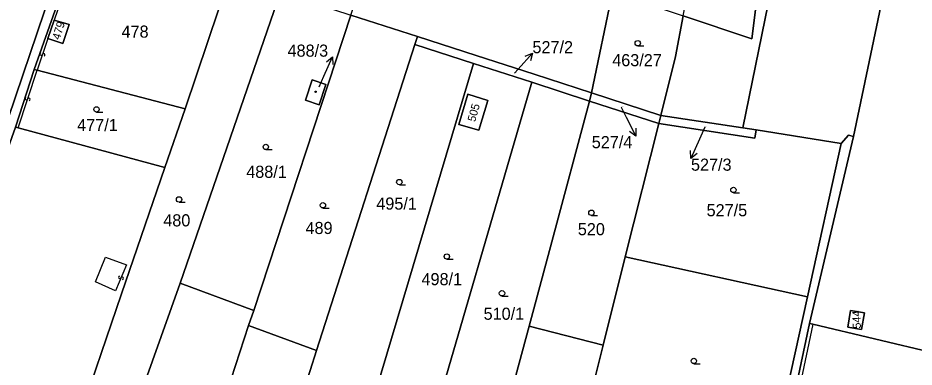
# Model space of a CAD drawing. Extents: x -600309 to -598967, y -1161267 to -1160292.
# Drawn here: x -599978 to -599852.3, y -1161077.3 to -1161028.3 of the extents above; entities that cross this region are included whole.
import ezdxf

# ---------------------------------------------------------------- set-up
doc = ezdxf.new("R2010")
doc.units = 0
for name, color, linetype in [('Level 1', 7, 'Continuous'), ('Level 13', 7, 'Continuous'), ('Level 3', 7, 'Continuous'), ('Level 4', 7, 'Continuous'), ('Level 5', 7, 'Continuous'), ('Level 57', 7, 'Continuous'), ('Level 60', 7, 'Continuous')]:
    doc.layers.add(name, color=color, linetype=linetype)

msp = doc.modelspace()

# ---------------------------------------------------------------- linework, layer by layer
at = {"layer": 'Level 1'}
for points in [[(-599876.36, -1161043.7), (-599856.42, -1160946.13), (-599839.99, -1160887.27), (-599850.14, -1160882.08)], [(-599860.84, -1161044.91), (-599844.27, -1160965.95)], [(-599884.69, -1161027.98), (-599875.08, -1161031.22), (-599871.19, -1161000.25), (-599876.49, -1160986.49)], [(-599987.63, -1161066.84), (-599982.42, -1161051.36), (-599970.18, -1161015.28)], [(-599968.71, -1161015.76), (-599975.67, -1161035.5)], [(-599948.21, -1161022.23), (-599954.53, -1161041.04)], [(-599941.17, -1161024.62), (-599955.2, -1161065.48)], [(-599897.54, -1161038.8), (-599894.62, -1161024.63)], [(-599972.87, -1161028.58), (-599970.76, -1161029.2), (-599971.67, -1161031.85), (-599973.77, -1161031.19)], [(-599973.77, -1161031.19), (-599972.87, -1161028.58)], [(-599931.3, -1161027.88), (-599944.9, -1161069.34)], [(-599931.3, -1161027.88), (-599921.93, -1161030.89)], [(-599884.69, -1161027.98), (-599885.79, -1161033.71), (-599887.83, -1161041.95)], [(-599921.93, -1161030.89), (-599922.3, -1161032.03)], [(-599921.93, -1161030.89), (-599913.74, -1161033.56), (-599905.6, -1161036.16), (-599897.54, -1161038.8)], [(-599922.3, -1161032.03), (-599936.1, -1161074.93)], [(-599922.3, -1161032.03), (-599914.08, -1161034.68)], [(-599914.08, -1161034.68), (-599927.85, -1161080.81)], [(-599914.08, -1161034.68), (-599905.93, -1161037.31)], [(-599975.67, -1161035.5), (-599978.31, -1161043.6)], [(-599975.67, -1161035.5), (-599975.27, -1161035.6)], [(-599975.27, -1161035.6), (-599954.53, -1161041.04)], [(-599936.71, -1161036.98), (-599934.81, -1161037.61), (-599935.75, -1161040.46), (-599937.65, -1161039.83), (-599936.71, -1161036.98)], [(-599905.93, -1161037.31), (-599921.39, -1161090.4)], [(-599905.93, -1161037.31), (-599897.85, -1161039.96)], [(-599914.87, -1161038.99), (-599912.09, -1161039.86), (-599913.34, -1161044.05), (-599916.13, -1161043.22), (-599914.87, -1161038.99)], [(-599897.85, -1161039.96), (-599903.12, -1161059.71), (-599906.31, -1161071.52)], [(-599897.54, -1161038.8), (-599897.85, -1161039.96)], [(-599897.85, -1161039.96), (-599888.12, -1161043.11)], [(-599897.54, -1161038.8), (-599887.83, -1161041.95)], [(-599954.53, -1161041.04), (-599957.36, -1161049.29)], [(-599888.12, -1161043.11), (-599887.83, -1161041.95)], [(-599887.83, -1161041.95), (-599876.36, -1161043.7)], [(-599977.92, -1161043.71), (-599978.31, -1161043.6)], [(-599957.36, -1161049.29), (-599977.92, -1161043.71)], [(-599888.12, -1161043.11), (-599892.84, -1161061.79)], [(-599888.12, -1161043.11), (-599874.67, -1161045.17), (-599874.48, -1161043.99)], [(-599876.36, -1161043.7), (-599874.48, -1161043.99)], [(-599874.48, -1161043.99), (-599862.56, -1161045.91)], [(-599867, -1161071.15), (-599860.84, -1161044.91)], [(-599862.56, -1161045.91), (-599861.52, -1161044.73), (-599860.84, -1161044.91)], [(-599862.56, -1161045.91), (-599867.28, -1161067.4)], [(-599969.84, -1161085.78), (-599963.43, -1161066.98), (-599957.36, -1161049.29)], [(-599895.94, -1161074.2), (-599892.84, -1161061.79)], [(-599892.84, -1161061.79), (-599867.28, -1161067.4)], [(-599955.2, -1161065.48), (-599962.99, -1161087.27)], [(-599955.2, -1161065.48), (-599944.9, -1161069.34)], [(-599867.28, -1161067.4), (-599877.21, -1161112.63)], [(-599944.9, -1161069.34), (-599945.61, -1161071.42)], [(-599861.26, -1161069.35), (-599859.28, -1161069.64), (-599859.69, -1161071.99), (-599861.6, -1161071.66), (-599861.26, -1161069.35)], [(-599872.88, -1161098.99), (-599867, -1161071.15)], [(-599866.54, -1161071.27), (-599867, -1161071.15)], [(-599845.34, -1161075.68), (-599849.26, -1161075.35), (-599866.54, -1161071.27)], [(-599945.61, -1161071.42), (-599948.08, -1161078.93)], [(-599936.1, -1161074.93), (-599945.61, -1161071.42)], [(-599906.31, -1161071.52), (-599914.53, -1161101.98)], [(-599906.31, -1161071.52), (-599895.94, -1161074.2)], [(-599936.1, -1161074.93), (-599936.97, -1161077.75)], [(-599895.94, -1161074.2), (-599903.23, -1161103.39)]]:
    msp.add_lwpolyline(points, dxfattribs=at)
at = {"layer": 'Level 13'}
for centre, start, end in [((-599974.69, -1161033.34), 108.3733, 340.9633), ((-599974.35, -1161033.46), 288.5877, 160.6857), ((-599976.77, -1161039.6), 109.2776, 341.3756), ((-599976.43, -1161039.72), 289.0631, 161.6531), ((-599963.68, -1161064.68), 104.5053, 337.0953), ((-599963.34, -1161064.82), 284.7198, 156.8178)]:
    msp.add_arc(centre, 0.184, start, end, dxfattribs=at)
at = {"layer": 'Level 3'}
for points in [[(-599968.48, -1161015.84), (-599972.87, -1161028.58)], [(-599973.77, -1161031.19), (-599975.27, -1161035.6)], [(-599977.92, -1161043.71), (-599975.27, -1161035.6)], [(-599967.09, -1161065.32), (-599965.69, -1161061.86), (-599962.74, -1161062.9), (-599964.28, -1161066.59), (-599967.09, -1161065.32)], [(-599866.54, -1161071.27), (-599872.38, -1161099)]]:
    msp.add_lwpolyline(points, dxfattribs=at)
at = {"layer": 'Level 5'}
for p, q in [((-599891.07, -1161032.21), (-599890.2, -1161032.21)), ((-599966.94, -1161041.49), (-599966.07, -1161041.49)), ((-599943.2, -1161046.76), (-599942.33, -1161046.76)), ((-599924.49, -1161051.69), (-599923.61, -1161051.69)), ((-599877.66, -1161052.8), (-599876.79, -1161052.8)), ((-599955.37, -1161054.13), (-599954.49, -1161054.13)), ((-599935.2, -1161054.95), (-599934.33, -1161054.95)), ((-599897.57, -1161056), (-599896.7, -1161056)), ((-599917.83, -1161062.13), (-599916.95, -1161062.13)), ((-599910.1, -1161067.3), (-599909.22, -1161067.3)), ((-599883.21, -1161076.79), (-599882.33, -1161076.79))]:
    msp.add_line(p, q, dxfattribs=at)
for centre, radius in [((-599891.07, -1161031.83), 0.375), ((-599936.23, -1161038.64), 0.09), ((-599936.23, -1161038.64), 0.0521), ((-599966.94, -1161041.11), 0.375), ((-599943.2, -1161046.38), 0.375), ((-599924.49, -1161051.31), 0.375), ((-599877.66, -1161052.42), 0.375), ((-599955.37, -1161053.75), 0.375), ((-599935.2, -1161054.57), 0.375), ((-599897.57, -1161055.62), 0.375), ((-599917.83, -1161061.75), 0.375), ((-599910.1, -1161066.92), 0.375), ((-599883.21, -1161076.41), 0.375)]:
    msp.add_circle(centre, radius, dxfattribs=at)
at = {"layer": 'Level 57'}
for p, q in [((-599907.83, -1161035.46), (-599905.83, -1161033.23)), ((-599935.07, -1161036.46), (-599933.85, -1161033.72)), ((-599908.33, -1161036.02), (-599907.83, -1161035.46)), ((-599935.72, -1161037.94), (-599935.07, -1161036.46)), ((-599893.41, -1161040.82), (-599892.7, -1161042.2)), ((-599892.7, -1161042.2), (-599891.32, -1161044.86)), ((-599881.68, -1161043.59), (-599882.41, -1161045.27)), ((-599882.41, -1161045.27), (-599883.61, -1161048.02))]:
    msp.add_line(p, q, dxfattribs=at)
for points in [[(-599906.87, -1161033.64), (-599905.83, -1161033.23), (-599906.12, -1161034.31)], [(-599934.71, -1161034.43), (-599933.85, -1161033.72), (-599933.8, -1161034.84)], [(-599891.33, -1161043.74), (-599891.32, -1161044.86), (-599892.22, -1161044.2)], [(-599882.75, -1161047.3), (-599883.61, -1161048.02), (-599883.67, -1161046.9)]]:
    msp.add_lwpolyline(points, dxfattribs=at)
at = {"layer": 'Level 60'}
for points in [[(-599844.27, -1160965.95), (-599860.84, -1161044.91), (-599861.52, -1161044.73), (-599862.56, -1161045.91), (-599874.48, -1161043.99), (-599876.36, -1161043.7), (-599856.42, -1160946.13), (-599839.99, -1160887.27), (-599850.14, -1160882.08), (-599827.83, -1160814.61), (-599810.16, -1160810.02), (-599816.36, -1160847.18), (-599843.15, -1160960.89)], [(-599853.73, -1160897.91), (-599855.26, -1160896.72), (-599850.14, -1160882.08), (-599839.99, -1160887.27), (-599856.42, -1160946.13), (-599876.36, -1161043.7), (-599887.83, -1161041.95), (-599885.79, -1161033.71), (-599884.69, -1161027.98), (-599875.08, -1161031.22), (-599871.19, -1161000.25), (-599876.49, -1160986.49), (-599876.14, -1160984.81), (-599874.2, -1160983.28), (-599869.25, -1160978.32), (-599867.01, -1160974.06), (-599865.26, -1160969.53), (-599852.15, -1160910.27), (-599851.34, -1160903.95)], [(-599843.15, -1160960.89), (-599827.13, -1160965.43), (-599827.7, -1160967.24), (-599825.39, -1160967.94), (-599824.75, -1160966.15), (-599821.88, -1160966.97), (-599822.87, -1160971.79), (-599825.9, -1160986.2), (-599831.06, -1161008.01), (-599832.98, -1161007.59), (-599833.44, -1161009.63), (-599831.55, -1161010.01), (-599837.23, -1161035.15), (-599845.34, -1161075.68), (-599849.26, -1161075.35), (-599866.54, -1161071.27), (-599867, -1161071.15), (-599860.84, -1161044.91), (-599844.27, -1160965.95)], [(-599871.19, -1161000.25), (-599875.08, -1161031.22), (-599884.69, -1161027.98), (-599876.49, -1160986.49)], [(-600026.92, -1160993.46), (-599990.21, -1161005.96), (-599990.65, -1161007.08), (-599990.72, -1161007.63), (-599989.7, -1161008.08), (-599989.91, -1161009.12), (-599988.76, -1161009.47), (-599970.18, -1161015.28), (-599982.42, -1161051.36), (-599987.63, -1161066.84), (-599993.68, -1161065.11), (-599995.07, -1161065.69), (-600005.59, -1161062.74), (-600019.19, -1161058.92), (-600026.96, -1161056.92), (-600037.48, -1161049.43), (-600041.18, -1161046.88), (-600042.22, -1161046.17), (-600028.44, -1160993.91), (-600027.9, -1160993.46)], [(-599941.17, -1161024.62), (-599948.21, -1161022.23), (-599968.48, -1161015.84), (-599967.79, -1161014.2), (-599965.04, -1161000.9), (-599894.62, -1161024.63), (-599897.54, -1161038.8), (-599905.6, -1161036.16), (-599913.74, -1161033.56), (-599921.93, -1161030.89), (-599931.3, -1161027.88), (-599927.2, -1161015.74), (-599927.09, -1161014.57), (-599936.77, -1161012.37), (-599944.6, -1161011.46), (-599944.73, -1161011.99), (-599937.41, -1161014.17)], [(-599970.18, -1161015.28), (-599968.71, -1161015.76), (-599975.67, -1161035.5), (-599978.31, -1161043.6), (-599981.21, -1161051.66), (-599986.44, -1161067.18), (-599987.63, -1161066.84), (-599982.42, -1161051.36)], [(-599975.67, -1161035.5), (-599968.71, -1161015.76), (-599968.48, -1161015.84), (-599948.21, -1161022.23), (-599954.53, -1161041.04), (-599975.27, -1161035.6)], [(-599969.84, -1161085.78), (-599963.43, -1161066.98), (-599957.36, -1161049.29), (-599954.53, -1161041.04), (-599948.21, -1161022.23), (-599941.17, -1161024.62), (-599955.2, -1161065.48), (-599962.99, -1161087.27)], [(-599955.2, -1161065.48), (-599941.17, -1161024.62), (-599931.3, -1161027.88), (-599944.9, -1161069.34)], [(-599887.83, -1161041.95), (-599897.54, -1161038.8), (-599894.62, -1161024.63), (-599884.69, -1161027.98), (-599885.79, -1161033.71)], [(-599970.76, -1161029.2), (-599972.87, -1161028.58), (-599973.77, -1161031.19), (-599971.67, -1161031.85)], [(-599972.87, -1161028.58), (-599970.76, -1161029.2), (-599971.67, -1161031.85), (-599973.77, -1161031.19)], [(-599945.61, -1161071.42), (-599944.9, -1161069.34), (-599931.3, -1161027.88), (-599921.93, -1161030.89), (-599922.3, -1161032.03), (-599936.1, -1161074.93)], [(-599922.3, -1161032.03), (-599921.93, -1161030.89), (-599913.74, -1161033.56), (-599905.6, -1161036.16), (-599897.54, -1161038.8), (-599897.85, -1161039.96), (-599905.93, -1161037.31), (-599914.08, -1161034.68)], [(-599936.1, -1161074.93), (-599922.3, -1161032.03), (-599914.08, -1161034.68), (-599927.85, -1161080.81), (-599929.9, -1161087.85), (-599932.34, -1161096.08), (-599932.61, -1161096.87), (-599939.08, -1161095.18), (-599935.69, -1161083.15), (-599938.49, -1161082.41), (-599936.97, -1161077.75)], [(-599927.85, -1161080.81), (-599914.08, -1161034.68), (-599905.93, -1161037.31), (-599921.39, -1161090.4), (-599929.9, -1161087.85)], [(-599975.67, -1161035.5), (-599975.27, -1161035.6), (-599954.53, -1161041.04), (-599957.36, -1161049.29), (-599977.92, -1161043.71), (-599978.31, -1161043.6)], [(-599934.81, -1161037.61), (-599936.71, -1161036.98), (-599937.65, -1161039.83), (-599935.75, -1161040.46)], [(-599936.71, -1161036.98), (-599934.81, -1161037.61), (-599935.75, -1161040.46), (-599937.65, -1161039.83)], [(-599921.39, -1161090.4), (-599905.93, -1161037.31), (-599897.85, -1161039.96), (-599903.12, -1161059.71), (-599906.31, -1161071.52), (-599914.53, -1161101.98), (-599915.77, -1161101.68), (-599916.12, -1161101.55), (-599923.97, -1161099.56), (-599923.94, -1161099.26), (-599923.9, -1161099.08), (-599922.86, -1161095.4)], [(-599912.09, -1161039.86), (-599914.87, -1161038.99), (-599916.13, -1161043.22), (-599913.34, -1161044.05)], [(-599914.87, -1161038.99), (-599912.09, -1161039.86), (-599913.34, -1161044.05), (-599916.13, -1161043.22)], [(-599903.12, -1161059.71), (-599897.85, -1161039.96), (-599888.12, -1161043.11), (-599892.84, -1161061.79), (-599895.94, -1161074.2), (-599906.31, -1161071.52)], [(-599897.54, -1161038.8), (-599887.83, -1161041.95), (-599888.12, -1161043.11), (-599897.85, -1161039.96)], [(-599876.36, -1161043.7), (-599874.48, -1161043.99), (-599874.67, -1161045.17), (-599888.12, -1161043.11), (-599887.83, -1161041.95)], [(-599997.96, -1161105.57), (-599998.39, -1161105.39), (-599997.17, -1161101.32), (-599989.35, -1161075.82), (-599986.44, -1161067.18), (-599981.21, -1161051.66), (-599978.31, -1161043.6), (-599977.92, -1161043.71), (-599957.36, -1161049.29), (-599963.43, -1161066.98), (-599969.84, -1161085.78), (-599970.99, -1161090.37), (-599971.18, -1161091.31), (-599975.49, -1161109.01), (-599976.16, -1161111.75), (-599991.07, -1161107.51), (-599994.63, -1161106.5)], [(-599867.28, -1161067.4), (-599892.84, -1161061.79), (-599888.12, -1161043.11), (-599874.67, -1161045.17), (-599874.48, -1161043.99), (-599862.56, -1161045.91)], [(-599885.77, -1161158.1), (-599887.19, -1161157.77), (-599884.35, -1161145.07), (-599882.93, -1161138.76), (-599881.84, -1161134.05), (-599878.49, -1161118.57), (-599877.21, -1161112.63), (-599867.28, -1161067.4), (-599862.56, -1161045.91), (-599861.52, -1161044.73), (-599860.84, -1161044.91), (-599867, -1161071.15), (-599872.88, -1161098.99), (-599876.8, -1161118.06), (-599881.8, -1161140.55), (-599882.48, -1161143.63), (-599883.3, -1161147.42)], [(-599903.65, -1161105.17), (-599903.23, -1161103.39), (-599895.94, -1161074.2), (-599892.84, -1161061.79), (-599867.28, -1161067.4), (-599877.21, -1161112.63), (-599887.6, -1161109.7)], [(-599962.99, -1161087.27), (-599955.2, -1161065.48), (-599944.9, -1161069.34), (-599945.61, -1161071.42), (-599948.08, -1161078.93), (-599948.37, -1161079.79), (-599952.69, -1161092.5), (-599953.21, -1161094.85), (-599953.98, -1161097.8), (-599954.48, -1161099.61), (-599956.23, -1161107.37), (-599958.51, -1161117.45), (-599958.1, -1161117.56), (-599958.19, -1161118), (-599958.64, -1161117.89), (-599958.82, -1161118.75), (-599959.06, -1161118.34), (-599965.44, -1161110.41), (-599966.28, -1161108.94), (-599967.23, -1161108.7), (-599962.71, -1161088.89), (-599963.46, -1161088.64)], [(-599859.28, -1161069.64), (-599861.26, -1161069.35), (-599861.6, -1161071.66), (-599859.69, -1161071.99)], [(-599861.26, -1161069.35), (-599859.28, -1161069.64), (-599859.69, -1161071.99), (-599861.6, -1161071.66)], [(-599849.26, -1161075.35), (-599845.34, -1161075.68), (-599851.75, -1161105.75), (-599852.17, -1161107.62), (-599852.63, -1161109.75), (-599854.09, -1161116.7), (-599864.18, -1161114.54), (-599866, -1161114.16), (-599864.38, -1161107.14), (-599864, -1161105.37), (-599862.53, -1161105.64), (-599861.52, -1161101.52), (-599867.19, -1161100.24), (-599872.38, -1161099), (-599872.88, -1161098.99), (-599867, -1161071.15), (-599866.54, -1161071.27)], [(-599948.08, -1161078.93), (-599945.61, -1161071.42), (-599936.1, -1161074.93), (-599936.97, -1161077.75), (-599938.49, -1161082.41), (-599935.69, -1161083.15), (-599939.08, -1161095.18), (-599939.17, -1161095.5), (-599939.28, -1161095.87), (-599942.59, -1161094.98), (-599943.75, -1161100.36), (-599953.71, -1161097.86), (-599953.98, -1161097.8), (-599953.21, -1161094.85), (-599952.69, -1161092.5), (-599948.37, -1161079.79)], [(-599903.23, -1161103.39), (-599911.83, -1161102.11), (-599913.49, -1161101.99), (-599914.07, -1161102.03), (-599914.53, -1161101.98), (-599906.31, -1161071.52), (-599895.94, -1161074.2)]]:
    msp.add_lwpolyline(points, close=True, dxfattribs=at)

# ---------------------------------------------------------------- texts
at = {"layer": 'Level 4'}
for s, rotation, p in [('479', 72.6238, (-599972.1, -1161031.43)), ('505', 74.3378, (-599913.87, -1161042.94)), ('544', 91.9252, (-599859.79, -1161071.86))]:
    msp.add_text(s, height=1.14, rotation=rotation, dxfattribs=at).set_placement(p)
for s, height, p in [('478', 1.7, (-599963.43, -1161031.05)), ('463/27', 1.7, (-599894.65, -1161035.06)), ('527/2', 0.1, (-599908.33, -1161036.02)), ('488/3', 0.1, (-599935.72, -1161037.94)), ('527/4', 0.1, (-599893.41, -1161040.82)), ('477/1', 1.7, (-599969.65, -1161044.16)), ('527/3', 0.1, (-599881.68, -1161043.59)), ('488/1', 1.7, (-599945.95, -1161050.72)), ('495/1', 1.7, (-599927.72, -1161055.18)), ('527/5', 1.7, (-599881.42, -1161056.11)), ('480', 1.7, (-599957.58, -1161057.53)), ('489', 1.7, (-599937.64, -1161058.6)), ('520', 1.7, (-599899.47, -1161058.77)), ('498/1', 1.7, (-599921.38, -1161065.78)), ('510/1', 1.7, (-599912.68, -1161070.63))]:
    msp.add_text(s, height=height, dxfattribs=at).set_placement(p)
at = {"layer": 'Level 57'}
for s, p in [('488/3', (-599940.16, -1161033.72)), ('527/2', (-599905.83, -1161033.23)), ('527/4', (-599897.52, -1161046.56)), ('527/3', (-599883.61, -1161049.72))]:
    msp.add_text(s, height=1.7, dxfattribs=at).set_placement(p)

doc.saveas('drawing.dxf')
